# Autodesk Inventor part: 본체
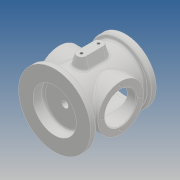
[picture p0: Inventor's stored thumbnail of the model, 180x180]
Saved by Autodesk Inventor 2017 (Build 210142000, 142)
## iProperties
Part Number: 본체
Material: 일반
Document SubType Name: Modeling
Designer: MRC
Density: 1 g/cm^3
Appearance: 기본값
Mass: 293.563 g
Surface Area: 770.717 cm^2
Volume: 293.563 cm^3
Author: MRC
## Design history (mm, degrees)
sketch "스케치1"
  geometry: C1 r 55 at (0, 0); 1 further point
  constraints: 1 centre point, 1 coincident
  dimensions: "d0" = 110 diameter of C1
extrude "돌출1" new body sketch "스케치1" distance "d1" = 10; taper "d2" = 0 deg
sketch "스케치2"
  geometry: C1 r 40 at (0, 0); 1 further point
  constraints: 1 centre point, 1 coincident
  dimensions: "d3" = 80 diameter of C1
extrude "돌출2" join sketch "스케치2" distance "d4" = 88; taper "d5" = 0 deg
sketch "스케치3"
  geometry: C1 r 47 at (0, 0); 1 further point
  constraints: 1 centre point, 1 coincident
  dimensions: "d6" = 94 diameter of C1
extrude "돌출3" join sketch "스케치3" distance "d7" = 10; taper "d8" = 0 deg
sketch "스케치4"
  geometry: L1 (0, 55)-(0, -55) reference; C1 r 35 at (54, 0); 1 further point
  constraints: 1 centre point, 1 horizontal alignment
  dimensions: "d9" = 70 diameter of C1; "d10" = 54 distance from line of L1 C1.centre
extrude "돌출4" join sketch "스케치4" stored distance "d11" = 94; taper "d12" = 0 deg
node "작업 평면1"
sketch "스케치5"
  geometry: L1 (0, 67)-(0, 41); L2 (-7, 67)-(-7, 41); L3 (7, 41)-(7, 67); L4 (-55, 0)-(55, 0) reference; A1 r 7 centre (0, 67) between (7, 67) and (-7, 67); A2 r 7 centre (0, 41) between (-7, 41) and (7, 41); 2 further points
  constraints: 8 end point, 4 point on circle, 4 tangent, 2 centre point, 1 midpoint, 1 parallel, 1 vertical, 1 vertical alignment
  dimensions: "d14" = 26 distance of L1.start L1.end; "d15" = 14 diameter of A2; "d16" = 54 distance from line of L4 point (0, 54)
extrude "돌출5" join sketch "스케치5" stored distance "d17" = 94; taper "d18" = 15 deg
hole "구멍1" diameter "d21" = 10; stored, may be unused: countersink angle "d25" = 90 deg, drill point angle "d27" = 118 deg; dims "d19" = 10, "d20" = 10, "d22" = 6, "d23" = 66, "d24" = 16, "d26" = 8
hole "구멍2" diameter "d30" = 66; stored, may be unused: countersink angle "d34" = 90 deg, drill point angle "d36" = 0 deg; dims "d31" = 6, "d32" = 70, "d33" = 7, "d35" = 86, "d93" = 10, "d94" = 10
hole "구멍3" diameter "d39" = 48; stored, may be unused: countersink angle "d43" = 90 deg, drill point angle "d45" = 0 deg; dims "d37" = 10, "d38" = 10, "d40" = 6, "d41" = 70, "d42" = 7, "d44" = 79
sketch "스케치6"
  geometry: C1 r 35 at (0, 0) reference; 2 further points
  constraints: 1 vertical alignment
  dimensions: "d46" = 29 distance of C1.centre point (0, 29)
hole "구멍4" sketch "스케치6" at (0, 29) diameter "d47" = 3.242; stored, may be unused: countersink angle "d51" = 90 deg, drill point angle "d53" = 118 deg; dims "d48" = 6, "d49" = 70, "d50" = 7, "d52" = 8
sketch "스케치7"
  geometry: C1 r 47 at (0, 0) reference; 2 further points
  constraints: 1 vertical alignment
  dimensions: "d57" = 40 distance of point (0, 0) point (0, 40)
hole "구멍5" sketch "스케치7" at (0, 40) diameter "d58" = 3.242; stored, may be unused: countersink angle "d62" = 90 deg, drill point angle "d64" = 118 deg; dims "d59" = 6, "d60" = 70, "d61" = 7, "d63" = 8
hole "구멍6" diameter "d70" = 4.134; stored, may be unused: countersink angle "d74" = 90 deg, drill point angle "d76" = 118 deg; dims "d68" = 10, "d69" = 10, "d71" = 6, "d72" = 70, "d73" = 7, "d75" = 8
hole "구멍7" diameter "d79" = 4.134; stored, may be unused: countersink angle "d83" = 90 deg, drill point angle "d85" = 118 deg; dims "d77" = 10, "d78" = 10, "d80" = 6, "d81" = 70, "d82" = 7, "d84" = 8
fillet "모깎기1" dims "d86" = 3
sketch "스케치8"
  geometry: C1 r 50 at (0, 0); 1 further point
  constraints: 1 centre point, 1 coincident, 1 other
  dimensions: "d87" = 100 diameter of C1
feature "엠보싱1" sketch "스케치8" dims "d88" = 0.5, "d89" = 0
chamfer "모따기1" distance "d90" = 1; stored, may be unused: second distance "d91" = 2, angle "d92" = 45 deg
node "솔리드1"
pattern_circular "원형 패턴1" dims angle "d55" = 360 deg
mirror "미러1"
pattern_circular "원형 패턴2" dims angle "d66" = 360 deg
other parameters: "d13" = 55
